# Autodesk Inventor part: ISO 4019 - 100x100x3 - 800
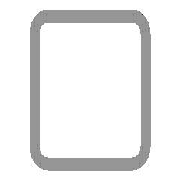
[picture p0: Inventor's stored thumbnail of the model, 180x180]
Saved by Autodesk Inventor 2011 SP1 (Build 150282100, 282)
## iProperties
IsCustomPart: 1
Created: 2010-02
Part Number: ISO 4019 - 100x100x3 - 800
Material: Steel, Mild
Description: Structural steels - Cold-formed, welded, structural hollow sections
Document SubType Name: Modeling
Standard: ISO 4019
Designer: SERGIO
Standard Revision: Second edition 2001-09-01
Standards Organization: ISO
Language: en-US
Size Designation: 100x100x3 - 800
Categories: <MemberInstance><Categories><Category DisplayName="Structural Shapes" InternalName="089c4875-fa83-4c05-b084-43b9cc11f5ed" Mnemonic="GRDR"><CategoryParameter Dis
Stock Number: 100x100x3
Density: 1 g/cm^3
G_L: 800,000 mm
Author: SERGIO
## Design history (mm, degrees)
node "Start plane"
node "End plane"
sketch "Sketch"
  geometry: L1 (-50, -44)-(-50, 44); L2 (-44, 50)-(44, 50); L3 (50, 44)-(50, -44); L4 (44, -50)-(-44, -50); L5 (-44, 47)-(44, 47); L6 (47, 44)-(47, -44); L7 (44, -47)-(-44, -47); L8 (-47, -44)-(-47, 44); L9 (0, 107.32)-(0, -107.32) reference; L10 (-107.32, 0)-(107.32, 0) reference; A1 r 6 centre (-44, -44) between (-50, -44) and (-44, -50); A2 r 6 centre (44, 44) between (50, 44) and (44, 50); A3 r 6 centre (-44, 44) between (-44, 50) and (-50, 44); A4 r 6 centre (44, -44) between (44, -50) and (50, -44); A5 r 3 centre (-44, 44) between (-44, 47) and (-47, 44); A6 r 3 centre (44, 44) between (47, 44) and (44, 47); A7 r 3 centre (44, -44) between (44, -47) and (47, -44); A8 r 3 centre (-44, -44) between (-47, -44) and (-44, -47)
  constraints: 16 end point, 16 point on circle, 8 centre point, 8 tangent, 4 parallel, 3 equal radius, 2 perpendicular, 7 other
  dimensions: "d7" = 6 radius of A1 (= G_IR); "d9" = 100 distance between parallel lines of L1 L3 (= G_W); "d11" = 100 distance between parallel lines of L2 L4 (= G_H); "d12" = 3 distance between parallel lines of L3 L6 (= G_T); "d15" = 50 distance between parallel lines of L9 L3 (= 0.5 x d9); "d16" = 50 distance between parallel lines of L2 L10 (= 0.5 x d11)
extrude "Body" new body sketch "Sketch" stored distance "d3" = 800 (= G_L); taper "d4" = 0 deg
node "Driven Length"
  sketch "Sketch3"
    geometry: L1 (0, 0)-(10, 0) reference
    constraints: 2 end point, 1 horizontal
  workplane "Work Plane3"
  sketch "Sketch4"
    geometry: L1 (-2, 0)-(12, 0) reference; L2 (-2, 800)-(12, 800) reference
    dimensions: "d18" = 800 distance between parallel lines of L1 L2 (derived)
sketch "Sketch5"
  geometry: L1 (88, 800)-(0, 800) reference; L2 (94, 0)-(94, 800) reference; L3 (44, 960)-(44, -160) reference; 5 further points
  constraints: 2 symmetric about line, 1 vertical alignment
  dimensions: "d19" = 25 distance from line of L1 point (74, 775); "d20" = 20 distance from line of point (74, 775) L2; "d21" = 50 distance of point (74, 725) point (74, 775)
hole "Hole1" sketch "Sketch5" at (74, 775), (74, 725), (14, 775), (14, 725) diameter "d22" = 6; stored, may be unused: countersink angle "d26" = 90 deg, drill point angle "d28" = 118 deg; dims "d23" = 6, "d24" = 4, "d25" = 2, "d27" = 8
body "Solid1"
other parameters: "G_W" = 100 [user parameter; used in 1 equation term], "G_H" = 100 [user parameter; used in 1 equation term], "G_T" = 3 [user parameter; used in 1 equation term], "G_IR" = 6 [user parameter; used in 1 equation term], "G_L" = 800 (= d18) [user parameter; used in 1 equation term], "G_OFFSET_START" = 0 [user parameter; used in 1 equation term], "G_OFFSET_END" = 0 [user parameter; used in 1 equation term], "d13" = 0 (computed from G_OFFSET_START), "d17" = 90 deg, "MAS" = 0.896 [user parameter]
